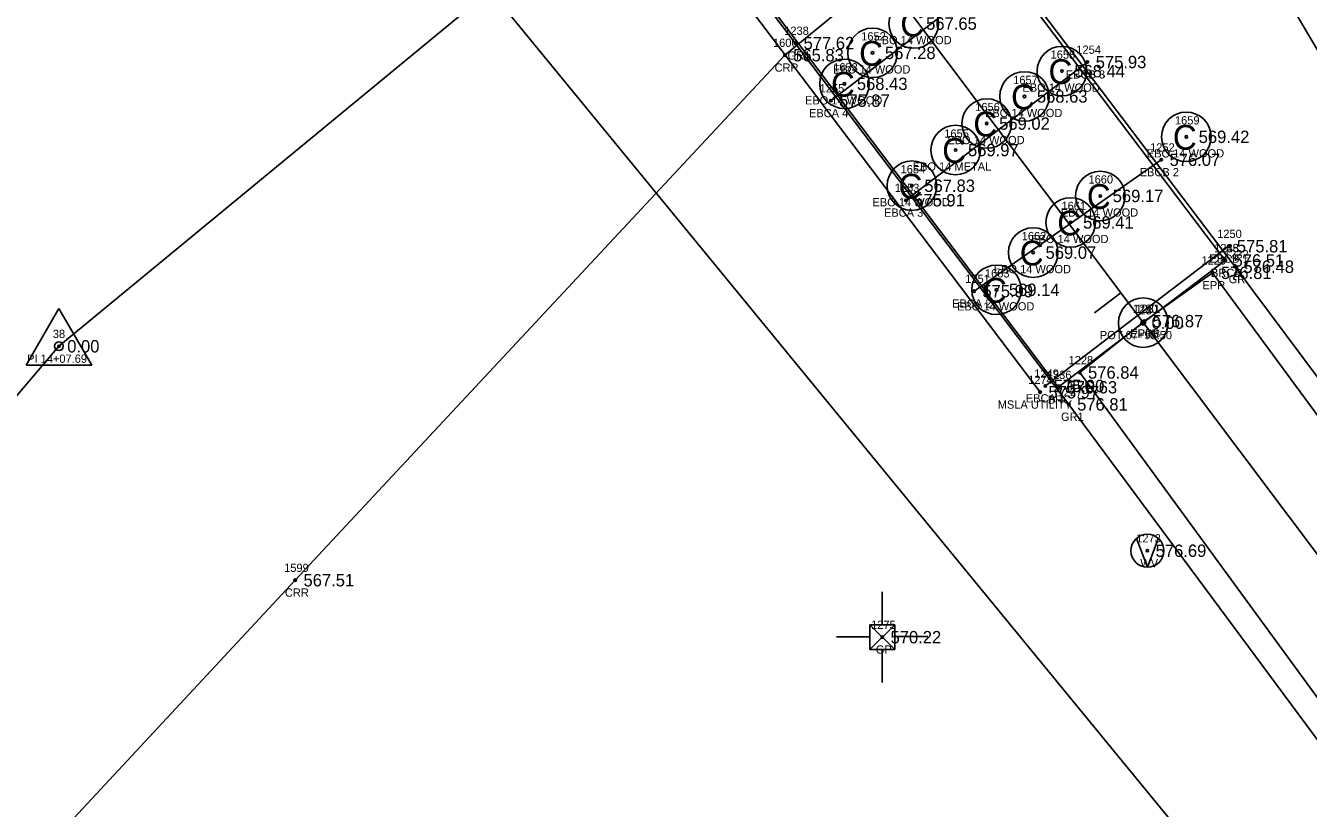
# Model space of a CAD drawing. Extents: x 1694813 to 1696862, y 1086485 to 1091027.
# Drawn here: x 1695795.8 to 1695951.1, y 1088933.9 to 1089028.7 of the extents above; entities that cross this region are included whole.
import ezdxf

# ---------------------------------------------------------------- set-up
doc = ezdxf.new("R2010")
doc.units = 0
for name, color, linetype in [('RD_EX_Bridge', 7, 'Continuous'), ('RD_EX_Bridge_txCode', 7, 'Continuous'), ('RD_EX_GuardRail', 7, 'Continuous'), ('RD_EX_GuardRail_txCode', 7, 'Continuous'), ('RD_EX_H2O', 7, 'Continuous'), ('RD_EX_H2O_txCode', 7, 'Continuous'), ('RD_EX_Misc', 7, 'Continuous'), ('RD_EX_Misc_txCode', 7, 'Continuous'), ('RD_EX_Road', 7, 'Continuous'), ('RD_EX_Road_txCode', 7, 'Continuous'), ('RD_EX_TX_Bridge_ELEV', 7, 'Continuous'), ('RD_EX_TX_GuardRail_ELEV', 7, 'Continuous'), ('RD_EX_TX_H2O_ELEV', 7, 'Continuous'), ('RD_EX_TX_Misc_ELEV', 7, 'Continuous'), ('RD_EX_TX_Road_ELEV', 7, 'Continuous'), ('RD_EX_TX_UT_ELEV', 7, 'Continuous'), ('RD_EX_UT', 7, 'Continuous'), ('RD_EX_UT_txCode', 7, 'Continuous'), ('RD_EX_VEG', 7, 'Continuous'), ('RD_HC_Cl', 7, 'Continuous'), ('RD_HC_Data', 7, 'Continuous'), ('RD_HC_Data_Tic', 7, 'Continuous'), ('RD_HC_Survey_ELEV', 7, 'Continuous'), ('RD_HC_txCode', 7, 'Continuous'), ('RD_SMD_Locator', 7, 'Continuous')]:
    doc.layers.add(name, color=color, linetype=linetype)

msp = doc.modelspace()

# ---------------------------------------------------------------- linework, layer by layer
at = {"layer": 'RD_EX_Bridge'}
for p, q in [((1695893.25, 1089019.58), (1695915.11, 1089036.39)), ((1695902.34, 1089007.52), (1695924.32, 1089024.26)), ((1695910.6, 1088996.51), (1695933.26, 1089012.42)), ((1695919.23, 1088985.03), (1695941.41, 1089001.95))]:
    msp.add_line(p, q, dxfattribs=at)
msp.add_lwpolyline([(1695941.01, 1089000.23), (1695920.78, 1088984.87), (1695803.35, 1089140.32), (1695823.67, 1089155.36), (1695941.01, 1089000.23)], dxfattribs=at)
for centre in [(1695903.29, 1089028.92), (1695898.3, 1089025.37), (1695921.23, 1089023.16), (1695894.9, 1089021.62), (1695916.7, 1089020.09), (1695912.13, 1089016.81), (1695936.29, 1089015.2), (1695908.36, 1089013.6), (1695903.07, 1089009.28), (1695925.88, 1089008.04), (1695922.29, 1089004.83), (1695917.75, 1089001.18), (1695913.31, 1088996.67)]:
    msp.add_circle(centre, 3, dxfattribs=at)
at = {"layer": 'RD_EX_GuardRail'}
for points in [[(1695954.25, 1088939.4), (1695922.07, 1088982.8), (1695888.95, 1089026.55), (1695824.62, 1089111.72), (1695774.33, 1089183.16), (1695747.02, 1089230.32), (1695728.79, 1089274.77), (1695712.04, 1089332.59)], [(1695975.12, 1088955.36), (1695942.2, 1088999.47), (1695910.75, 1089040.94), (1695844.49, 1089129.18), (1695795.31, 1089197.37)]]:
    msp.add_lwpolyline(points, dxfattribs=at)
at = {"layer": 'RD_EX_H2O'}
msp.add_lwpolyline([(1695520.92, 1088704.05), (1695627.53, 1088770.84), (1695697.51, 1088817.15), (1695757.08, 1088884.85), (1695828.4, 1088961.5), (1695887.69, 1089025.09), (1695910.13, 1089043.49), (1695963.83, 1089083.42), (1696041.69, 1089105.91), (1696137.07, 1089082.48), (1696174.24, 1089034.61), (1696185.76, 1089011.54), (1696200.45, 1088973.14), (1696214.06, 1088899.28)], dxfattribs=at)
at = {"layer": 'RD_EX_Misc'}
msp.add_line((1695918.59, 1088984.27), (1695801.38, 1089139.4), dxfattribs=at)
at = {"layer": 'RD_EX_Road'}
for points in [[(1695879.87, 1087561.29), (1695893.33, 1087665.71), (1695905.96, 1087767.16), (1695918.66, 1087869.54), (1695930.87, 1087972.82), (1695936.26, 1088023.68), (1695942.14, 1088076.32), (1695948.07, 1088128.17), (1695955.04, 1088181.4), (1695962.88, 1088230.72), (1695971.68, 1088284.64), (1695982.02, 1088336.12), (1695993.28, 1088388.48), (1696018.75, 1088494.48), (1696045.23, 1088599.95), (1696055.72, 1088654.41), (1696060.15, 1088705.35), (1696055.83, 1088758.02), (1696044.01, 1088812.16), (1696026.4, 1088860.33), (1696000.41, 1088911.48), (1695972.46, 1088953.82), (1695939.48, 1088998.73), (1695931.21, 1088992.88)], [(1696024.81, 1088603.86), (1696034.83, 1088656.78), (1696038.52, 1088705.77), (1696034.91, 1088754.94), (1696023.53, 1088806.4), (1696006.7, 1088851.13), (1695981.74, 1088901.12), (1695956.26, 1088941.69), (1695923.39, 1088986.66), (1695931.21, 1088992.88)]]:
    msp.add_lwpolyline(points, dxfattribs=at)
at = {"layer": 'RD_EX_UT'}
for p, q in [((1695931.58, 1088963.08), (1695930.27, 1088966.56)), ((1695931.58, 1088963.08), (1695932.9, 1088966.52)), ((1695899.48, 1088956.1), (1695899.48, 1088960.1)), ((1695900.98, 1088956.1), (1695897.98, 1088953.1)), ((1695897.98, 1088956.1), (1695900.98, 1088953.1)), ((1695900.98, 1088956.1), (1695897.98, 1088956.1)), ((1695897.98, 1088956.1), (1695897.98, 1088953.1)), ((1695900.98, 1088953.1), (1695900.98, 1088956.1)), ((1695897.95, 1088954.65), (1695893.95, 1088954.65)), ((1695900.99, 1088954.67), (1695905.01, 1088954.67)), ((1695897.98, 1088953.1), (1695900.98, 1088953.1)), ((1695899.48, 1088953.1), (1695899.48, 1088949.1))]:
    msp.add_line(p, q, dxfattribs=at)
msp.add_circle((1695931.58, 1088965.07), 2, dxfattribs=at)
at = {"layer": 'RD_EX_VEG'}
for points in [[(1695767.04, 1087738.17), (1695850.84, 1087719.29), (1695876.92, 1087874.52), (1695886.77, 1087978.73), (1695882.04, 1088123.19), (1695966.35, 1088397.22), (1695987.61, 1088500.99), (1696016.82, 1088604.01), (1696023.94, 1088658.84), (1696026.75, 1088706.17), (1696020.44, 1088756.26), (1696012.04, 1088803.02), (1695995.69, 1088847.32), (1695967.16, 1088892.48), (1695790.95, 1089107.47), (1695767.01, 1089177.35), (1695741.24, 1089223.37), (1695720.39, 1089271.33), (1695703.52, 1089329.03), (1695695, 1089381.13)], [(1695933.86, 1087837.25), (1695947.67, 1087971.41), (1695951.18, 1088015.29), (1695955.07, 1088071.66), (1695974.95, 1088229.99), (1695984.06, 1088281.51), (1695991.57, 1088334), (1696002.15, 1088386.49), (1696032.05, 1088491.59), (1696059.12, 1088595.39), (1696074.06, 1088653.09), (1696077.62, 1088703.57), (1696070.4, 1088760.42), (1696059.88, 1088817.29), (1696044.37, 1088867.3), (1696013.5, 1088916.36), (1695990.24, 1088961.27), (1695859.14, 1089183.28), (1695912, 1089200.8)]]:
    msp.add_lwpolyline(points, dxfattribs=at)
at = {"layer": 'RD_HC_Cl'}
for p, q in [((1695971.3, 1088939.1), (1695801.51, 1089165.33)), ((1695799.79, 1088989.83), (1695937.83, 1089103.75)), ((1695670.22, 1088837.9), (1695799.79, 1088989.83))]:
    msp.add_line(p, q, dxfattribs=at)
at = {"layer": 'RD_HC_Data'}
for p, q in [((1695795.82, 1088987.53), (1695799.79, 1088994.41)), ((1695799.79, 1088994.41), (1695803.76, 1088987.53)), ((1695795.82, 1088987.53), (1695803.76, 1088987.53))]:
    msp.add_line(p, q, dxfattribs=at)
for centre, radius in [((1695931.08, 1088992.69), 3), ((1695931.08, 1088992.69), 0.282), ((1695799.79, 1088989.83), 0.529)]:
    msp.add_circle(centre, radius, dxfattribs=at)
at = {"layer": 'RD_HC_Data_Tic'}
msp.add_line((1695928.38, 1088996.29), (1695925.18, 1088993.89), dxfattribs=at)
at = {"layer": 'RD_SMD_Locator'}
for centre in [(1695888.95, 1089026.55), (1695887.69, 1089025.09), (1695898.3, 1089025.37), (1695924.32, 1089024.26), (1695894.9, 1089021.62), (1695921.23, 1089023.16), (1695916.7, 1089020.09), (1695893.25, 1089019.58), (1695912.13, 1089016.81), (1695936.29, 1089015.2), (1695908.36, 1089013.6), (1695933.26, 1089012.42), (1695903.07, 1089009.28), (1695925.88, 1089008.04), (1695902.34, 1089007.52), (1695922.29, 1089004.83), (1695941.41, 1089001.95), (1695917.75, 1089001.18), (1695941.01, 1089000.23), (1695941.01, 1089000.23), (1695939.48, 1088998.73), (1695942.2, 1088999.47), (1695910.6, 1088996.51), (1695913.31, 1088996.67), (1695931.08, 1088992.69), (1695931.21, 1088992.88), (1695931.21, 1088992.88), (1695799.79, 1088989.83), (1695923.39, 1088986.66), (1695919.23, 1088985.03), (1695920.78, 1088984.87), (1695918.59, 1088984.27), (1695922.07, 1088982.8), (1695931.58, 1088965.07), (1695828.4, 1088961.5), (1695899.48, 1088954.6)]:
    msp.add_circle(centre, 0.15, dxfattribs=at)

# ---------------------------------------------------------------- texts
at = {"layer": 'RD_EX_Bridge'}
for p in [(1695901.66, 1089027.36), (1695896.67, 1089023.81), (1695919.6, 1089021.6), (1695893.27, 1089020.06), (1695915.07, 1089018.53), (1695910.5, 1089015.25), (1695934.66, 1089013.64), (1695906.73, 1089012.04), (1695901.44, 1089007.72), (1695924.25, 1089006.47), (1695920.66, 1089003.27), (1695916.12, 1088999.62), (1695911.68, 1088995.1)]:
    msp.add_text('C', height=3, dxfattribs=at).set_placement(p)
at = {"layer": 'RD_EX_Bridge_txCode'}
for s, p in [('1652', (1695896.93, 1089026.87)), ('EBO 14 WOOD', (1695898.51, 1089026.42)), ('1658', (1695919.86, 1089024.66)), ('1254', (1695922.98, 1089025.26)), ('1653', (1695893.53, 1089023.12)), ('EBO 14 WOOD', (1695893.52, 1089022.87)), ('1657', (1695915.33, 1089021.59)), ('EBCB 3', (1695921.7, 1089022.26)), ('1255', (1695891.9, 1089020.58)), ('EBO 14 WOOD', (1695916.45, 1089020.66)), ('EBO 14 WOOD', (1695890.12, 1089019.12)), ('1656', (1695910.73, 1089018.31)), ('EBCA 4', (1695890.6, 1089017.58)), ('EBO 14 WOOD', (1695911.92, 1089017.59)), ('1659', (1695934.92, 1089016.7)), ('1655', (1695906.99, 1089015.1)), ('EBO 14 WOOD', (1695907.35, 1089014.31)), ('1252', (1695931.91, 1089013.42)), ('EBO 14 WOOD', (1695931.51, 1089012.7)), ('1654', (1695901.7, 1089010.78)), ('EBO 14 METAL', (1695903.16, 1089011.1)), ('EBCB 2', (1695930.64, 1089010.42)), ('1253', (1695900.99, 1089008.52)), ('1660', (1695924.45, 1089009.54)), ('EBO 14 WOOD', (1695898.29, 1089006.78)), ('EBCA 3', (1695899.68, 1089005.52)), ('EBO 14 WOOD', (1695921.1, 1089005.54)), ('1661', (1695921.18, 1089006.33)), ('1662', (1695916.36, 1089002.68)), ('EBO 14 WOOD', (1695917.51, 1089002.33)), ('1250', (1695940.03, 1089002.95)), ('1235', (1695939.67, 1089001.23)), ('1248', (1695939.67, 1089001.23)), ('EBCB 1', (1695939.07, 1088999.95)), ('1251', (1695909.53, 1088997.51)), ('1663', (1695911.91, 1088998.17)), ('EBO 14 WOOD', (1695912.97, 1088998.68)), ('BRCA', (1695939.27, 1088998.23)), ('BRCB', (1695939.29, 1088998.23)), ('EBCA 2', (1695907.94, 1088994.51)), ('EBO 14 WOOD', (1695908.53, 1088994.17)), ('1249', (1695917.89, 1088986.03)), ('1236', (1695919.41, 1088985.87)), ('EBCA 1', (1695916.86, 1088983.03)), ('BRC', (1695919.52, 1088982.87))]:
    msp.add_text(s, height=1, dxfattribs=at).set_placement(p)
at = {"layer": 'RD_EX_GuardRail_txCode'}
for s, p in [('1238', (1695887.61, 1089027.55)), ('GR1', (1695888.01, 1089024.55)), ('1232', (1695940.86, 1089000.47)), ('GR', (1695941.42, 1088997.47)), ('1227', (1695920.72, 1088983.8)), ('GR1', (1695921.12, 1088980.8))]:
    msp.add_text(s, height=1, dxfattribs=at).set_placement(p)
at = {"layer": 'RD_EX_H2O_txCode'}
for s, p in [('1600', (1695886.25, 1089026.09)), ('CRR', (1695886.44, 1089023.09)), ('1599', (1695827.06, 1088962.5)), ('CRR', (1695827.15, 1088959.5))]:
    msp.add_text(s, height=1, dxfattribs=at).set_placement(p)
at = {"layer": 'RD_EX_Misc_txCode'}
for s, p in [('1274', (1695917.14, 1088985.27)), ('MSLA UTILITY', (1695913.46, 1088982.27))]:
    msp.add_text(s, height=1, dxfattribs=at).set_placement(p)
at = {"layer": 'RD_EX_Road_txCode'}
for s, p in [('1229', (1695938.13, 1088999.73)), ('EPR', (1695938.25, 1088996.73)), ('1230', (1695929.82, 1088993.88)), ('1231', (1695930.14, 1088993.88)), ('EPRB', (1695929.5, 1088990.88)), ('EPLB', (1695929.53, 1088990.88)), ('1228', (1695922.04, 1088987.66)), ('EPL', (1695922.18, 1088984.66))]:
    msp.add_text(s, height=1, dxfattribs=at).set_placement(p)
at = {"layer": 'RD_EX_TX_Bridge_ELEV'}
for s, p in [('567.65', (1695904.79, 1089028.17)), ('567.28', (1695899.8, 1089024.62)), ('575.93', (1695925.32, 1089023.51)), ('568.44', (1695922.73, 1089022.41)), ('568.43', (1695896.4, 1089020.87)), ('575.87', (1695894.25, 1089018.83)), ('568.63', (1695918.2, 1089019.34)), ('569.02', (1695913.63, 1089016.06)), ('569.42', (1695937.79, 1089014.45)), ('569.97', (1695909.86, 1089012.85)), ('576.07', (1695934.26, 1089011.67)), ('567.83', (1695904.57, 1089008.53)), ('575.91', (1695903.34, 1089006.77)), ('569.17', (1695927.38, 1089007.29)), ('569.41', (1695923.79, 1089004.08)), ('569.07', (1695919.25, 1089000.43)), ('575.81', (1695942.41, 1089001.2)), ('576.51', (1695942.01, 1088999.48)), ('576.51', (1695942.01, 1088999.48)), ('575.99', (1695911.6, 1088995.76)), ('569.14', (1695914.81, 1088995.92)), ('575.90', (1695920.23, 1088984.28)), ('576.63', (1695921.78, 1088984.12))]:
    msp.add_text(s, height=1.5, dxfattribs=at).set_placement(p)
at = {"layer": 'RD_EX_TX_GuardRail_ELEV'}
for s, p in [('577.62', (1695889.95, 1089025.8)), ('576.48', (1695943.2, 1088998.72)), ('576.81', (1695923.07, 1088982.05))]:
    msp.add_text(s, height=1.5, dxfattribs=at).set_placement(p)
at = {"layer": 'RD_EX_TX_H2O_ELEV'}
for s, p in [('565.83', (1695888.69, 1089024.34)), ('567.51', (1695829.4, 1088960.75))]:
    msp.add_text(s, height=1.5, dxfattribs=at).set_placement(p)
at = {"layer": 'RD_EX_TX_Misc_ELEV'}
msp.add_text('575.97', height=1.5, dxfattribs=at).set_placement((1695919.59, 1088983.52))
at = {"layer": 'RD_EX_TX_Road_ELEV'}
for s, p in [('576.81', (1695940.48, 1088997.98)), ('576.87', (1695932.21, 1088992.13)), ('576.87', (1695932.21, 1088992.13)), ('576.84', (1695924.39, 1088985.91))]:
    msp.add_text(s, height=1.5, dxfattribs=at).set_placement(p)
at = {"layer": 'RD_EX_TX_UT_ELEV'}
for s, p in [('576.69', (1695932.58, 1088964.32)), ('570.22', (1695900.48, 1088953.85))]:
    msp.add_text(s, height=1.5, dxfattribs=at).set_placement(p)
at = {"layer": 'RD_EX_UT_txCode'}
for s, p in [('1273', (1695930.23, 1088966.07)), ('WV', (1695930.72, 1088963.07)), ('1275', (1695898.13, 1088955.6)), ('GP', (1695898.7, 1088952.6))]:
    msp.add_text(s, height=1, dxfattribs=at).set_placement(p)
at = {"layer": 'RD_HC_Survey_ELEV'}
for p in [(1695932.08, 1088991.94), (1695800.79, 1088989.08)]:
    msp.add_text('0.00', height=1.5, dxfattribs=at).set_placement(p)
at = {"layer": 'RD_HC_txCode'}
for s, p in [('18', (1695930.63, 1088993.69)), ('38', (1695799.05, 1088990.83)), ('POT 67+95.50', (1695925.82, 1088990.69)), ('PI 14+07.69', (1695795.94, 1088987.83))]:
    msp.add_text(s, height=1, dxfattribs=at).set_placement(p)

doc.saveas('drawing.dxf')
